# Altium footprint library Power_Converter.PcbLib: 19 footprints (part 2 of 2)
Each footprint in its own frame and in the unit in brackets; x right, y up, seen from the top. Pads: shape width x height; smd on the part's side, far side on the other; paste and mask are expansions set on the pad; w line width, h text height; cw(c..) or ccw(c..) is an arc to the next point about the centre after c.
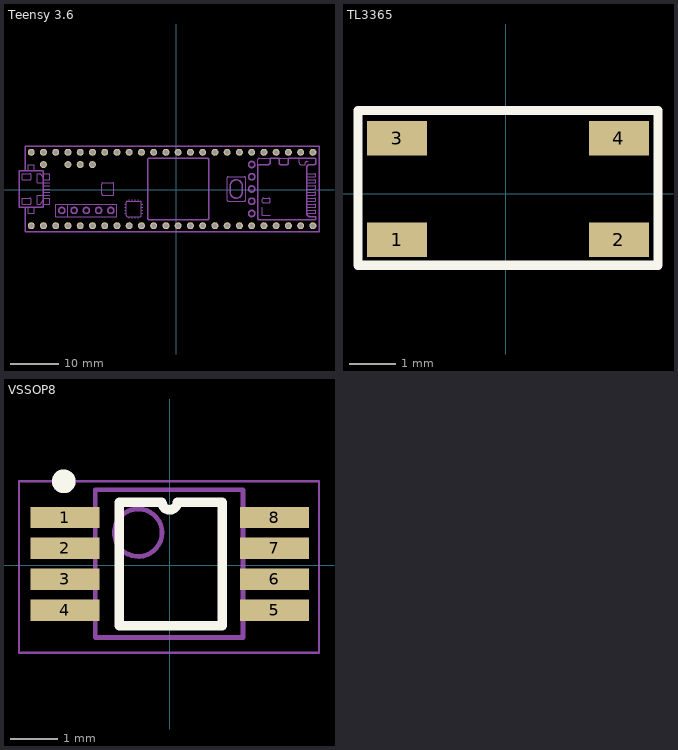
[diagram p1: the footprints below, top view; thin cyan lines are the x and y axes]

## Teensy 3.6 [mil]
pads (52):
  round 57 hole 38: 0/RX(-1085,-295) 1/TX(-985,-295) 2(-885,-295) 3/CANTX(-785,-295) 3V3(215,-295) 3V3_LO(-985,305) 4/CANRX(-685,-295) 5(-585,-295) 6(-485,-295) 7(-385,-295) 8(-285,-295) 9/CS(-185,-295) 10/CS(-85,-295) 11/MOSI(15,-295) 12/MISO(115,-295) 13/SCK(115,305) 14/A0(15,305) 15/A1(-85,305) 16/A2(-185,305) 17/A3(-285,305) 18/A4/SDA(-385,305) 19/A5/SCL(-485,305) 20/A6(-585,305) 21/A7(-685,305) 21/DAC0(415,305) 22/A8(-785,305) 23/A9(-885,305) 24(315,-295) 25(415,-295) 26(515,-295) 27(615,-295) 28(715,-295) 29(815,-295) 30(915,-295) 31/A12(1015,-295) 32/A13(1115,-295) 33/A14(1115,305) 34/A15(1015,305) 35/A16(915,305) 36/A17(815,305) 37/A18(715,305) 38/A19(615,305) 39/A20(515,305) A10(-785,205) A11(-685,205) A22/DAC1(315,305) AGND(-1085,305) AREF(-885,205) GND(-1185,-295) GND2(215,305) VIN(-1185,305) VUSB(-1085,205)
Mechanical 2:
  drawing of 245 lines, arcs and shapes, not listed

## TL3365 [mm] "Pushbutton"
pads (4):
  rect 1.3x0.75 smd: 1(-2.35,-1) 2(2.45,-1) 3(-2.35,1.2) 4(2.45,1.2)
Top Overlay:
  lines w0.2: -3.2,-1.55 -3.2,1.8 3.3,1.8 3.3,-1.55 -3.2,-1.55

## VSSOP8 [mm]
pads (8):
  rect 1.45x0.45 smd: 1(-2.2,1) 2(-2.2,0.35) 3(-2.2,-0.3) 4(-2.2,-0.95) 5(2.2,-0.95) 6(2.2,-0.3) 7(2.2,0.35) 8(2.2,1)
Top Overlay:
  circle w0.25: c-2.225,1.76 r0.125
  lines w0.2: -1.057,-1.275 1.102,-1.275 1.102,1.325 0.162,1.325 cw(c0,1.325) -0.163,1.325 -1.057,1.325 -1.057,-1.275
Mechanical 13:
  circle w0.1: c-0.661,0.681 r0.5
  lines w0.1: -1.561,-1.519 1.539,-1.519 1.539,1.581 -1.561,1.581 -1.561,-1.519
Mechanical 15:
  lines w0.05: -3.164,-1.838 3.136,-1.838 3.136,1.762 -3.164,1.762 -3.164,-1.838
3D body: height 1.1, standoff 0.15, extent -1.561,-1.519 1.539,1.581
